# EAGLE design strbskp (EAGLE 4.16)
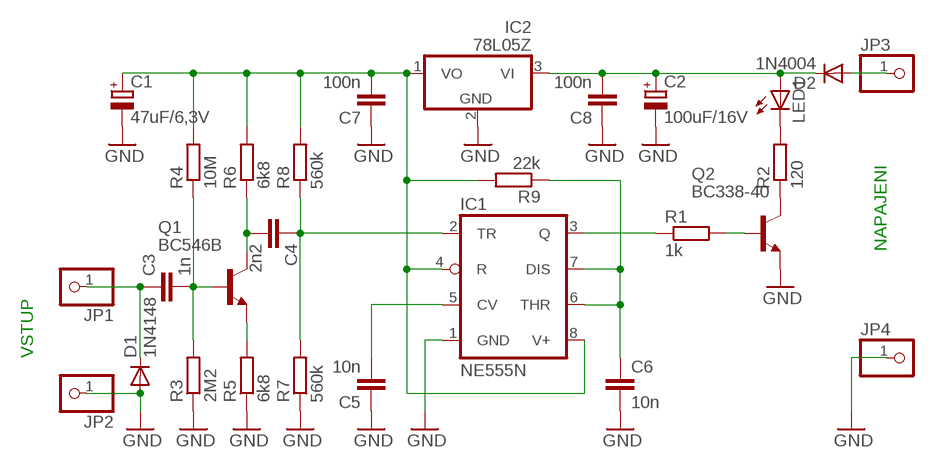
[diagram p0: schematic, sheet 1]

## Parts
C1  47uF/6,3V  CPOL-EUSANYO_B  [SANYO-OSCON_B]
C2  100uF/16V  CPOL-EUSANYO_B  [SANYO-OSCON_B]
C3  1n  C-EU050-024X044  [C050-024X044]
C4  2n2  C-EU050-024X044  [C050-024X044]
C5  10n  C-EU050-024X044  [C050-024X044]
C6  10n  C-EU050-024X044  [C050-024X044]
C7  100n  C-EU050-024X044  [C050-024X044]
C8  100n  C-EU050-024X044  [C050-024X044]
D1  1N4148  [DO35-10]
D2  1N4004  [DO41-10]
IC1  NE555N  [DIL08]
IC2  78L05Z  [TO92]
JP1  PINHD-1X1  [1X01]
JP2  PINHD-1X1  [1X01]
JP3  PINHD-1X1  [1X01]
JP4  PINHD-1X1  [1X01]
LED1  LED5MM  [LED5MM]
Q1  BC546B  [TO92-EBC]
Q2  BC338-40  [TO92-EBC]
R1  1k  R-EU_0207/7  [0207/7]
R2  120  R-EU_0207/7  [0207/7]
R3  2M2  R-EU_0207/7  [0207/7]
R4  10M  R-EU_0207/7  [0207/7]
R5  6k8  R-EU_0207/7  [0207/7]
R6  6k8  R-EU_0207/7  [0207/7]
R7  560k  R-EU_0207/7  [0207/7]
R8  560k  R-EU_0207/7  [0207/7]
R9  22k  R-EU_0207/7  [0207/7]

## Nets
GND: C1.- C2.- C5.1 C6.2 C7.1 C8.1 D1.A IC1.1(GND) IC2.2(GND) JP2.1 JP4.1 Q2.E R3.1 R5.1 R7.1
N$1: IC1.3(Q) R1.1
N$2: Q1.E R5.2
N$3: Q2.C R2.1
N$4: C3.1 D1.C JP1.1
N$5: C2.+ C8.2 D2.C IC2.3(VI) LED1.A
N$6: Q2.B R1.2
N$7: C5.2 IC1.5(CV)
N$8: C6.1 IC1.6(THR) IC1.7(DIS) R9.1
N$9: C1.+ C7.2 IC1.4(R) IC1.8(V+) IC2.1(VO) R4.2 R6.2 R8.2 R9.2
N$10: C4.2 Q1.C R6.1
N$11: C3.2 Q1.B R3.2 R4.1
N$12: C4.1 IC1.2(TR) R7.2 R8.1
N$13: LED1.K(C) R2.2
N$14: D2.A JP3.1

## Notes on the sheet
- NAPAJENI
- VSTUP

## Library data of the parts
C1 C2 = rcl:CPOL-EU: POLARIZED CAPACITOR, European symbol
C3-C8 = rcl:C-EU: CAPACITOR, European symbol
D1 = diode:1N4148: DIODE
D2 = diode:1N4004: DIODE
IC1 = linear:*555: TIMER
IC2 = linear:78*: Positive VOLTAGE REGULATOR Source: http://cache.national.com/ds/LM/LM78L05.pdf http://www.fairchildsemi.com/ds/LM/LM7805.pdf
JP1-JP4 = pinhead:PINHD-1X1: PIN HEADER
LED1 = led:LED: LED
Q1 = transistor-npn:BC546*: NPN Transistor
Q2 = transistor-npn:BC338*: NPN Transistor
R1-R9 = rcl:R-EU_: RESISTOR, European symbol

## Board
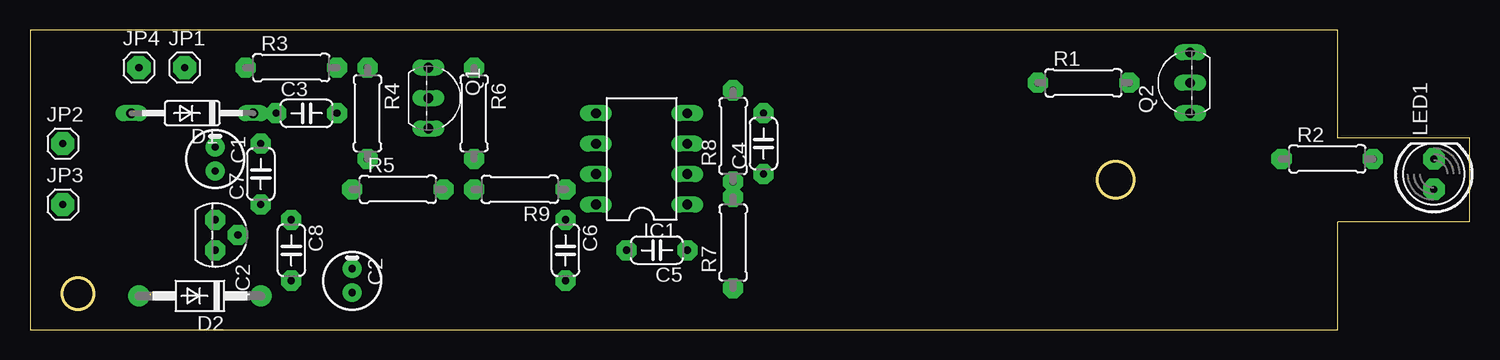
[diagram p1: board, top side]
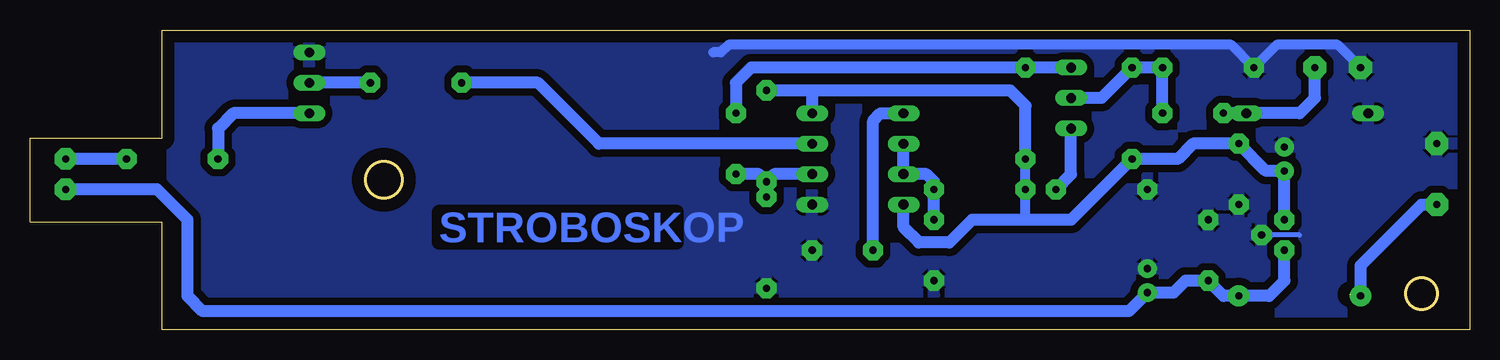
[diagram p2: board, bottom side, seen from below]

Size 120 x 25 mm. Coordinates in mm from the lower left corner, seen from the top.
Outline: 10,3 10,2.9
Outline: 109,0 109,9 120,9 120,16 109,16 109,25 0,25 0,0 109,0
Outline: circle at 4,3 radius 1.3
Outline: circle at 90.5,12.5 radius 1.5
Copper layers (1*16): Top 0.035mm / dielectric 1.5mm / Bottom 0.035mm
Design rules "default": minimum track width 10mil, minimum drill 24mil, track to track 8mil, track to pad 8mil, pad to pad 8mil, via to via 8mil, smd to smd 8mil, copper to edge 40mil, drill to drill 8mil, minimum pad ring 10mil, minimum via ring 8mil, stop-mask expansion 4mil, vias tented up to drill 0mil, thermal gap 10mil

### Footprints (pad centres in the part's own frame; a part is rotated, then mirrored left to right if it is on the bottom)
SANYO-OSCON_B = drill 0.6 pad 1.575 round: + 1,0; - -1,0
C050-024X044 = drill 0.6 pad 1.676 octagon: 1 -2.54,0; 2 2.54,0
DO35-10 = drill 0.813 long: A 5.08,0; C -5.08,0
DO41-10 = drill 0.6 pad 1.778 round: A 5.08,0; C -5.08,0
DIL08 = drill 0.813 long: 1 -3.81,-3.81; 2 -1.27,-3.81; 3 1.27,-3.81; 4 3.81,-3.81; 5 3.81,3.81; 6 1.27,3.81; 7 -1.27,3.81; 8 -3.81,3.81
TO92 = drill 0.6 pad 1.676 octagon: 1 -1.27,0; 2 0,1.905; 3 1.27,0
1X01 = drill 0.6 pad 1.93 octagon: 1 0,0
LED5MM = drill 0.6 pad 1.778 octagon: A -1.27,0; K 1.27,0
TO92-EBC = drill 0.813 long: B 0,-1.27; C -2.54,-1.27; E 2.54,-1.27
0207/7 = drill 0.6 pad 1.676 octagon: 1 -3.81,0; 2 3.81,0

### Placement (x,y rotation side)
C1  15.43,14.24 270 top
C2  26.86,4.08 270 top
C3  23.05,18.05 0 top
C4  61.15,15.51 90 top
C5  52.26,6.62 180 top
C6  44.64,6.62 270 top
C7  19.24,12.97 90 top
C8  21.78,6.62 270 top
D1  13.53,18.05 180 top
D2  14.16,2.81 180 top
IC1  50.99,14.24 90 top
IC2  15.43,7.89 270 top
JP1  12.89,21.86 0 top
JP2  2.73,15.51 0 top
JP3  2.73,10.43 0 top
JP4  9.08,21.86 0 top
LED1  117.03,12.97 90 top
Q1  34.48,19.32 270 top
Q2  95.44,20.59 90 top
R1  87.82,20.59 0 top
R2  108.14,14.24 0 top
R3  21.78,21.86 0 top
R4  28.13,18.05 270 top
R5  30.67,11.7 0 top
R6  37.02,18.05 270 top
R7  58.61,7.26 90 top
R8  58.61,16.14 90 top
R9  40.83,11.7 180 top

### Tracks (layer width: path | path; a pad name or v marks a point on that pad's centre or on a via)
GND
  Bottom 0.406: 14.16,7.89 IC2.2
  Bottom 0.813: JP4.1 10.98,23.77 16.06,23.77 R3.1 19.88,23.77 61.78,23.77 62.42,23.13 63.05,23.13
  pour Bottom (isolate 0.61): 1.46,25.04 108.14,25.04 108.14,0.27 1.46,0.27
N$1
  Bottom 1.016: IC1.3 72.58,15.51 77.66,20.59 R1.1
N$2
  Bottom 1.016: R5.2 33.21,12.97 Q1.E
N$3
  Bottom 1.016: R2.1 104.33,16.78 103.06,18.05 Q2.C
N$4
  Bottom 1.016: JP1.1 12.89,19.32 14.16,18.05 D1.C C3.1
N$5
  Bottom 1.016: IC2.3 15.43,4.08 16.7,2.81 D2.C 20.51,2.81 C8.2 23.68,4.08 24.68,3.08 C2.+ 28.4,1.54 105.6,1.54 106.87,2.81 106.87,9.16 109.41,11.7 LED1.A
N$6
  Bottom 1.016: R1.2 Q2.B
N$7
  Bottom 1.016: IC1.5 49.09,18.05 49.72,17.41 C5.2
N$8
  Bottom 1.016: IC1.6 IC1.7 45.27,12.97 44.64,12.34 R9.1 C6.1
N$9
  Bottom 0.813: 37.02,9.16 R9.2 R6.2
  Bottom 1.016: IC2.1 C1.+ 16.97,13.24 C7.2 23.05,15.51 24.32,14.24 R4.2 33.21,9.16 37.02,9.16 41.47,9.16 43.37,7.26 45.91,7.26 47.18,8.53 IC1.8 | 54.8,19.95 R8.2 | 54.8,19.95 IC1.4 | R6.2 37.02,18.68 38.29,19.95 54.8,19.95
N$10
  Bottom 1.016: Q1.C R6.1 59.88,21.86 61.15,20.59 C4.2
N$11
  Bottom 1.016: Q1.B 30.67,19.32 R4.1 R3.2 C3.2
N$12
  Bottom 1.016: IC1.2 57.98,12.97 R8.1 | R8.1 59.24,12.97 C4.1 | R8.1 R7.2
N$13
  Bottom 1.016: R2.2 LED1.K
N$14
  Bottom 1.016: JP3.1 4,10.43 9.08,5.35 D2.A

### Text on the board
Bottom: STROBOSKOP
